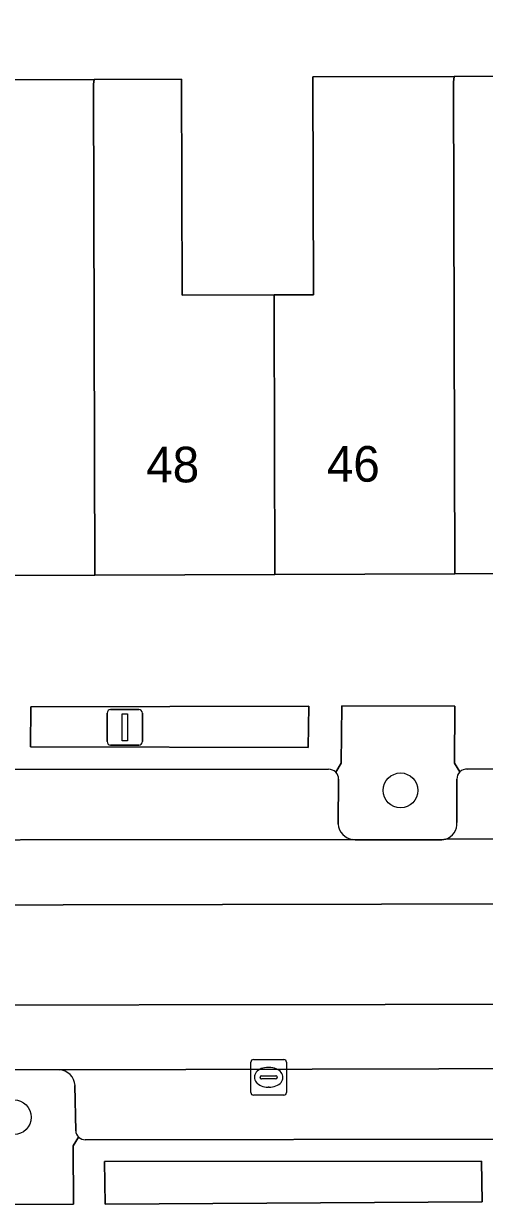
# Model space of a CAD drawing. Extents: x 159716 to 160783, y 383290 to 384031.
# Drawn here: x 160190.54 to 160203.47, y 383749.04 to 383782.17 of the extents above; entities that cross this region are included whole.
import ezdxf

# ---------------------------------------------------------------- set-up
doc = ezdxf.new("R2010")
doc.units = 0
for name, color, linetype in [('IMGEO_Boom', 7, 'Continuous'), ('IMGEO_Erf', 7, 'Continuous'), ('IMGEO_Groenvoorziening', 7, 'Continuous'), ('IMGEO_Kolk', 7, 'Continuous'), ('IMGEO_Lichtmast', 7, 'Continuous'), ('IMGEO_Pand', 7, 'Continuous'), ('IMGEO_Pand_nummerreeks', 7, 'Continuous'), ('IMGEO_Parkeervlak_open', 7, 'Continuous'), ('IMGEO_Rijbaan_lokaal_gesloten', 7, 'Continuous'), ('IMGEO_Rijbaan_lokaal_open', 7, 'Continuous'), ('IMGEO_Voetpad_open', 7, 'Continuous')]:
    doc.layers.add(name, color=color, linetype=linetype)

msp = doc.modelspace()

# ---------------------------------------------------------------- linework, layer by layer
at = {"layer": 'IMGEO_Boom'}
for centre in [(160201.119, 383760.655), (160190.265, 383751.486)]:
    msp.add_circle(centre, 0.489, dxfattribs=at)
at = {"layer": 'IMGEO_Erf'}
msp.add_lwpolyline([(160188.65, 383780.592), (160192.519, 383780.604), (160194.971, 383780.612), (160194.989, 383774.547), (160197.569, 383774.555), (160198.675, 383774.559), (160198.656, 383780.676), (160202.62, 383780.688), (160205.053, 383780.695), (160205.071, 383774.592), (160207.673, 383774.6), (160208.756, 383774.602), (160208.738, 383780.695), (160212.707, 383780.707), (160215.068, 383780.713), (160215.087, 383774.599), (160216.767, 383774.604), (160216.75, 383780.76), (160217.76, 383780.763), (160220.025, 383780.77), (160220.043, 383774.644), (160222.714, 383774.658), (160222.518, 383788.206)], dxfattribs=at)
at = {"layer": 'IMGEO_Groenvoorziening'}
for points in [[(160198.528, 383761.86), (160198.544, 383763.017), (160190.744, 383762.998), (160190.734, 383761.873)], [(160192.83, 383749.044), (160203.415, 383749.112), (160203.39, 383750.254), (160192.811, 383750.244)]]:
    msp.add_lwpolyline(points, close=True, dxfattribs=at)
for points in [[(160202.782, 383761.172), (160202.631, 383761.421), (160202.644, 383763.019), (160199.472, 383763.024), (160199.453, 383761.417), (160199.303, 383761.164)], [(160199.381, 383760.97), (160199.368, 383759.711)], [(160202.703, 383759.754), (160202.702, 383760.969)], [(160199.78, 383759.275), (160199.841, 383759.271), (160202.275, 383759.268), (160202.386, 383759.29)], [(160191.536, 383752.818), (160188.342, 383752.821), (160188.351, 383751.62), (160188.37, 383749.041), (160191.936, 383749.049), (160191.93, 383750.685)], [(160192, 383751.106), (160191.981, 383752.376)], [(160191.93, 383750.685), (160192.083, 383750.93)]]:
    msp.add_lwpolyline(points, dxfattribs=at)
for centre, radius, start, end in [((160199.106, 383760.972), 0.275, 359.5958, 44.2106), ((160202.976, 383760.978), 0.274, 135.0296, 181.9527), ((160199.844, 383759.748), 0.477, 184.4495, 262.3082), ((160202.244, 383759.727), 0.46, 288.0105, 3.3085), ((160191.511, 383752.347), 0.471, 3.4843, 86.9033), ((160192.267, 383751.124), 0.267, 183.9026, 226.5937)]:
    msp.add_arc(centre, radius, start, end, dxfattribs=at)
at = {"layer": 'IMGEO_Kolk'}
for p, q in [((160196.916, 383752.18), (160196.916, 383753.032)), ((160196.991, 383753.106), (160197.843, 383753.106)), ((160197.917, 383753.032), (160197.917, 383752.18)), ((160197.218, 383752.649), (160197.616, 383752.649)), ((160197.404, 383752.886), (160197.429, 383752.886)), ((160197.175, 383752.6), (160197.175, 383752.612)), ((160197.613, 383752.563), (160197.215, 383752.563)), ((160197.427, 383752.326), (160197.402, 383752.326)), ((160197.659, 383752.612), (160197.659, 383752.6)), ((160197.843, 383752.106), (160196.991, 383752.106))]:
    msp.add_line(p, q, dxfattribs=at)
for points in [[(160196.916, 383752.18), (160196.916, 383753.032)], [(160196.991, 383753.106), (160197.843, 383753.106)], [(160197.917, 383753.032), (160197.917, 383752.18)], [(160197.843, 383752.106), (160196.991, 383752.106)]]:
    msp.add_lwpolyline(points, dxfattribs=at)
for centre, radius, start, end in [((160196.993, 383753.03), 0.0765, 91.552, 178.448), ((160196.993, 383753.03), 0.0765, 91.552, 178.448), ((160197.841, 383753.03), 0.0765, 1.552, 88.448), ((160197.841, 383753.03), 0.0765, 1.552, 88.448), ((160197.215, 383752.609), 0.0403, 85.8775, 175.7526), ((160197.62, 383752.611), 0.0386, 1.7309, 96.639), ((160197.212, 383752.599), 0.0366, 178.938, 274.7102), ((160197.616, 383752.606), 0.043, 264.8664, 352.4533), ((160196.993, 383752.182), 0.0765, 181.552, 268.448), ((160196.993, 383752.182), 0.0765, 181.552, 268.448), ((160197.841, 383752.182), 0.0765, 271.552, 358.448), ((160197.841, 383752.182), 0.0765, 271.552, 358.448)]:
    msp.add_arc(centre, radius, start, end, dxfattribs=at)
for centre, major_axis, ratio, start_param, end_param in [((160197.403, 383752.606), (-0.387, 0.002), 0.722429, 4.712389, 7.853982), ((160197.428, 383752.606), (-0.39, 0.002), 0.717154, 1.570796, 4.712389)]:
    msp.add_ellipse(centre, major_axis=major_axis, ratio=ratio, start_param=start_param, end_param=end_param, dxfattribs=at)
at = {"layer": 'IMGEO_Lichtmast'}
for p, q in [((160192.982, 383762.925), (160193.772, 383762.925)), ((160193.772, 383762.925), (160192.982, 383762.925)), ((160192.882, 383762.025), (160192.882, 383762.825)), ((160192.882, 383762.825), (160192.882, 383762.025)), ((160193.872, 383762.825), (160193.872, 383762.025)), ((160193.872, 383762.025), (160193.872, 383762.825)), ((160193.772, 383761.925), (160192.982, 383761.925)), ((160192.982, 383761.925), (160193.772, 383761.925))]:
    msp.add_line(p, q, dxfattribs=at)
msp.add_lwpolyline([(160193.302, 383762.8), (160193.452, 383762.8), (160193.452, 383762.05), (160193.302, 383762.05), (160193.302, 383762.8)], dxfattribs=at)
for centre, start, end in [((160192.982, 383762.825), 90, 180), ((160192.982, 383762.825), 90, 180), ((160193.772, 383762.825), 0, 90), ((160193.772, 383762.825), 360, 90), ((160192.982, 383762.025), 180, 270), ((160192.982, 383762.025), 180, 270), ((160193.772, 383762.025), 270, 0), ((160193.772, 383762.025), 270, 0)]:
    msp.add_arc(centre, 0.1, start, end, dxfattribs=at)
at = {"layer": 'IMGEO_Pand'}
for points in [[(160192.499, 383780.473), (160192.519, 383780.604), (160188.65, 383780.592), (160188.668, 383774.545), (160187.465, 383774.542), (160187.466, 383774.036), (160187.489, 383766.677), (160192.54, 383766.696)], [(160197.57, 383774.083), (160197.569, 383774.555), (160194.989, 383774.547), (160194.971, 383780.612), (160192.519, 383780.604), (160192.499, 383780.473), (160192.54, 383766.696), (160197.592, 383766.714)], [(160202.604, 383780.524), (160202.62, 383780.688), (160198.656, 383780.676), (160198.675, 383774.559), (160197.569, 383774.555), (160197.57, 383774.083), (160197.592, 383766.714), (160202.645, 383766.732)], [(160207.673, 383774.156), (160207.673, 383774.6), (160205.071, 383774.592), (160205.053, 383780.695), (160202.62, 383780.688), (160202.604, 383780.524), (160202.645, 383766.732), (160207.696, 383766.751)]]:
    msp.add_lwpolyline(points, close=True, dxfattribs=at)
at = {"layer": 'IMGEO_Parkeervlak_open'}
for points in [[(160220.965, 383761.292), (160202.998, 383761.253)], [(160199.098, 383761.248), (160181.722, 383761.242)], [(160199.368, 383759.711), (160199.381, 383760.97)], [(160202.702, 383760.969), (160202.703, 383759.754)], [(160181.107, 383759.263), (160199.78, 383759.275)], [(160202.386, 383759.29), (160221.555, 383759.33)], [(160216.4, 383752.881), (160191.536, 383752.818)], [(160191.981, 383752.376), (160192, 383751.106)], [(160192.271, 383750.853), (160215.68, 383750.891)]]:
    msp.add_lwpolyline(points, dxfattribs=at)
for centre, radius, start, end in [((160199.102, 383760.966), 0.282, 44.601, 90.8357), ((160199.106, 383760.972), 0.275, 359.5958, 44.2106), ((160202.976, 383760.978), 0.274, 135.0296, 181.9527), ((160202.978, 383760.977), 0.277, 85.942, 135.1701), ((160199.844, 383759.748), 0.477, 184.4495, 262.3082), ((160202.244, 383759.727), 0.46, 288.0105, 3.3085), ((160191.511, 383752.347), 0.471, 3.4843, 86.9033), ((160192.267, 383751.124), 0.267, 183.9026, 226.5937), ((160192.272, 383751.124), 0.271, 225.6963, 269.7582)]:
    msp.add_arc(centre, radius, start, end, dxfattribs=at)
at = {"layer": 'IMGEO_Rijbaan_lokaal_gesloten'}
for points in [[(160221.555, 383759.33), (160202.386, 383759.29), (160202.275, 383759.268), (160199.841, 383759.271), (160199.78, 383759.275), (160181.107, 383759.263), (160180.979, 383759.258), (160179.364, 383759.264), (160179.252, 383759.269), (160160.584, 383759.235), (160160.499, 383759.227), (160159.176, 383759.229), (160159.178, 383757.411), (160191.646, 383757.443), (160213.991, 383757.492), (160248.823, 383757.529)], [(160217.399, 383754.672), (160214.509, 383754.669), (160159.216, 383754.597), (160159.216, 383752.77), (160159.632, 383752.773), (160159.72, 383752.765), (160172.365, 383752.793)], [(160172.511, 383752.802), (160175.525, 383752.831), (160175.584, 383752.825), (160182.471, 383752.837), (160182.549, 383752.845), (160188.342, 383752.821), (160191.536, 383752.818), (160216.4, 383752.881), (160217.406, 383752.866), (160217.399, 383754.672)]]:
    msp.add_lwpolyline(points, dxfattribs=at)
at = {"layer": 'IMGEO_Rijbaan_lokaal_open'}
msp.add_lwpolyline([(160248.823, 383757.529), (160213.991, 383757.492), (160191.646, 383757.443), (160159.178, 383757.411), (160159.176, 383759.229), (160158.775, 383759.23), (160158.811, 383752.767), (160159.216, 383752.77), (160159.216, 383754.597), (160214.509, 383754.669), (160217.399, 383754.672), (160217.406, 383752.866), (160218.477, 383752.851), (160218.678, 383752.842)], dxfattribs=at)
at = {"layer": 'IMGEO_Voetpad_open'}
for points in [[(160229.326, 383766.817), (160223.905, 383766.809), (160222.761, 383766.805), (160218.305, 383766.789), (160217.801, 383766.787), (160212.748, 383766.769), (160207.696, 383766.751), (160202.645, 383766.732), (160197.592, 383766.714), (160192.54, 383766.696), (160187.489, 383766.677), (160182.436, 383766.66), (160177.384, 383766.641), (160172.333, 383766.622), (160167.28, 383766.605), (160161.895, 383766.585), (160157.896, 383766.597), (160148.677, 383766.755)], [(160199.303, 383761.164), (160199.453, 383761.417), (160199.472, 383763.024), (160202.644, 383763.019), (160202.631, 383761.421), (160202.782, 383761.172)], [(160202.998, 383761.253), (160220.965, 383761.292)], [(160181.722, 383761.242), (160199.098, 383761.248)], [(160192.083, 383750.93), (160191.93, 383750.685), (160191.936, 383749.049), (160188.37, 383749.041), (160188.351, 383751.62)], [(160215.68, 383750.891), (160192.271, 383750.853)]]:
    msp.add_lwpolyline(points, dxfattribs=at)
for points in [[(160198.544, 383763.017), (160198.528, 383761.86), (160190.734, 383761.873), (160190.744, 383762.998)], [(160192.811, 383750.244), (160203.39, 383750.254), (160203.415, 383749.112), (160192.83, 383749.044)]]:
    msp.add_lwpolyline(points, close=True, dxfattribs=at)
for centre, radius, start, end in [((160199.102, 383760.966), 0.282, 44.601, 90.8357), ((160202.978, 383760.977), 0.277, 85.942, 135.1701), ((160192.272, 383751.124), 0.271, 225.6963, 269.7582)]:
    msp.add_arc(centre, radius, start, end, dxfattribs=at)

# ---------------------------------------------------------------- texts
at = {"layer": 'IMGEO_Pand_nummerreeks'}
for s, p in [('48', (160193.981, 383769.293)), ('46', (160199.05, 383769.312))]:
    msp.add_text(s, height=1, rotation=0.212, dxfattribs=at).set_placement(p)

doc.saveas('drawing.dxf')
